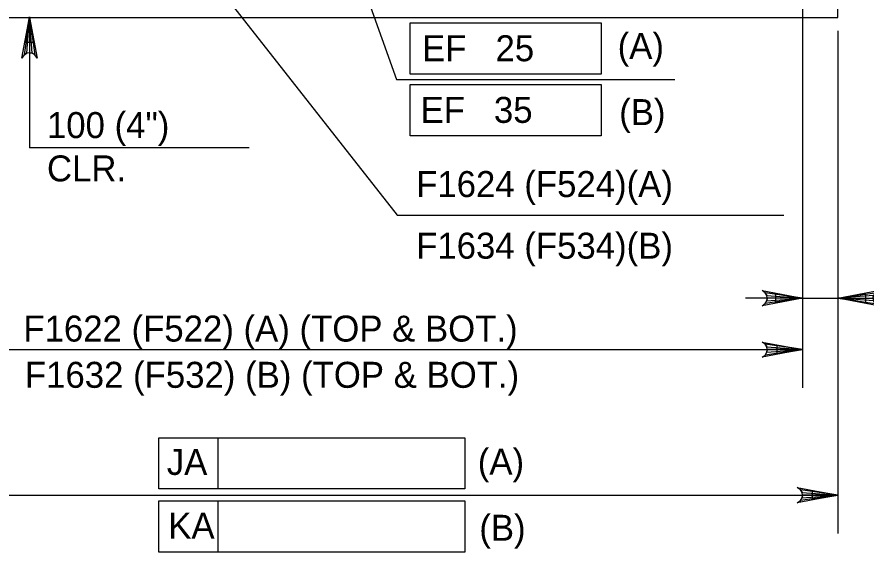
# Model space of a CAD drawing. Extents: x 634540 to 640306, y 296059 to 300275.
# Drawn here: x 639950.5 to 640048.5, y 298123.5 to 298185.3 of the extents above; entities that cross this region are included whole.
import ezdxf

# ---------------------------------------------------------------- set-up
doc = ezdxf.new("R2010")
doc.units = 0
for name, color, linetype in [('3', 7, 'Continuous'), ('4', 7, 'Continuous'), ('6', 7, 'Continuous'), ('9', 7, 'Continuous')]:
    doc.layers.add(name, color=color, linetype=linetype)

msp = doc.modelspace()

# ---------------------------------------------------------------- linework, layer by layer
at = {"layer": '4'}
for p, q in [((639964.766, 298200.154), (639994.343, 298162.419)), ((639989.636, 298191.057), (639994.297, 298178.094)), ((640041.155, 298188.247), (640041.155, 298142.484)), ((639995.87, 298184.624), (640017.91, 298184.624)), ((639995.87, 298178.717), (639995.87, 298184.624)), ((640017.91, 298184.624), (640017.91, 298178.717)), ((640045.22, 298183.697), (640045.22, 298125.682)), ((639951.891, 298182.901), (639951.891, 298170.206)), ((640017.91, 298178.717), (639995.87, 298178.717)), ((639994.297, 298178.094), (640026.409, 298178.094)), ((639995.87, 298177.511), (640017.91, 298177.511)), ((639995.87, 298171.604), (639995.87, 298177.511)), ((640017.91, 298177.511), (640017.91, 298171.604)), ((640017.91, 298171.604), (639995.87, 298171.604)), ((640045.22, 298163.383), (640045.22, 298151.891)), ((639994.343, 298162.419), (640039.009, 298162.419)), ((640041.155, 298152.847), (640034.565, 298152.847)), ((640041.155, 298152.847), (640074.917, 298152.847)), ((639935.009, 298146.914), (640041.155, 298146.914)), ((639966.86, 298136.74), (640002.162, 298136.74)), ((639966.86, 298130.834), (639966.86, 298136.74)), ((639973.704, 298130.834), (639973.704, 298136.74)), ((640002.162, 298136.74), (640002.162, 298130.834)), ((640002.162, 298130.834), (639966.86, 298130.834)), ((639930.942, 298130.111), (640045.22, 298130.111)), ((639966.86, 298129.455), (640002.162, 298129.455)), ((639966.86, 298123.548), (639966.86, 298129.455)), ((639973.704, 298123.548), (639973.704, 298129.455)), ((640002.162, 298129.455), (640002.162, 298123.548)), ((640002.162, 298123.548), (639966.86, 298123.548))]:
    msp.add_line(p, q, dxfattribs=at)
for points in [[(639951.903, 298185.234), (639952.778, 298180.574), (639952.528, 298180.932), (639952.216, 298181.117), (639951.903, 298181.172), (639951.591, 298181.117), (639951.278, 298180.932), (639951.03, 298180.574), (639951.903, 298185.234), (639951.278, 298180.932), (639951.591, 298181.117), (639951.903, 298185.234), (639951.903, 298181.172), (639952.216, 298181.117), (639951.903, 298185.234), (639952.528, 298180.932)], [(640041.155, 298152.847), (640036.495, 298151.974), (640036.853, 298152.222), (640037.038, 298152.535), (640037.093, 298152.847), (640037.038, 298153.16), (640036.853, 298153.472), (640036.495, 298153.72), (640041.155, 298152.847), (640036.853, 298153.472), (640037.038, 298153.16), (640041.155, 298152.847), (640037.093, 298152.847), (640037.038, 298152.535), (640041.155, 298152.847), (640036.853, 298152.222)], [(640045.22, 298152.847), (640049.881, 298153.72), (640049.522, 298153.472), (640049.337, 298153.16), (640049.283, 298152.847), (640049.337, 298152.535), (640049.522, 298152.222), (640049.881, 298151.974), (640045.22, 298152.847), (640049.522, 298152.222), (640049.337, 298152.535), (640045.22, 298152.847), (640049.283, 298152.847), (640049.337, 298153.16), (640045.22, 298152.847), (640049.522, 298153.472)], [(640041.155, 298146.914), (640036.495, 298146.041), (640036.853, 298146.289), (640037.038, 298146.601), (640037.093, 298146.914), (640037.038, 298147.226), (640036.853, 298147.539), (640036.495, 298147.787), (640041.155, 298146.914), (640036.853, 298147.539), (640037.038, 298147.226), (640041.155, 298146.914), (640037.093, 298146.914), (640037.038, 298146.601), (640041.155, 298146.914), (640036.853, 298146.289)], [(640045.22, 298130.111), (640040.559, 298129.238), (640040.918, 298129.486), (640041.103, 298129.798), (640041.157, 298130.111), (640041.103, 298130.423), (640040.918, 298130.736), (640040.559, 298130.984), (640045.22, 298130.111), (640040.918, 298130.736), (640041.103, 298130.423), (640045.22, 298130.111), (640041.157, 298130.111), (640041.103, 298129.798), (640045.22, 298130.111), (640040.918, 298129.486)]]:
    msp.add_lwpolyline(points, dxfattribs=at)
for points in [[(639952.382, 298182.359), (639951.399, 298182.359), (639951.891, 298185.311)], [(640038.068, 298152.356), (640038.068, 298153.341), (640041.02, 298152.847)], [(640048.447, 298153.341), (640048.447, 298152.356), (640045.495, 298152.847)], [(640038.203, 298147.405), (640038.203, 298146.422), (640041.155, 298146.914)], [(640042.268, 298130.603), (640042.268, 298129.619), (640045.22, 298130.111)]]:
    msp.add_lwpolyline(points, close=True, dxfattribs=at)
at = {"layer": '6'}
msp.add_line((639977.264, 298170.207), (639951.892, 298170.207), dxfattribs=at)
at = {"layer": '9'}
for p, q in [((640045.22, 298185.234), (640045.22, 298209.842)), ((639930.942, 298185.234), (640045.22, 298185.234))]:
    msp.add_line(p, q, dxfattribs=at)

# ---------------------------------------------------------------- texts
at = {"layer": '3'}
for s, p in [('100 (4")', (639953.924, 298171.334)), ('CLR.', (639953.924, 298166.333))]:
    msp.add_text(s, height=3.0001, dxfattribs=at).set_placement(p)
at = {"layer": '4'}
for s, height, p in [('(A)', 3.0001, (640019.815, 298180.476)), ('EF   25', 3.0001, (639997.241, 298180.203)), ('EF   35', 3.0001, (639997.059, 298173.088)), ('(B)', 3.0001, (640019.992, 298172.832)), ('F1624 (F524)(A)', 3.00014, (639996.547, 298164.525)), ('F1634 (F534)(B)', 3.00014, (639996.547, 298157.412)), ('F1622 (F522) (A) (TOP & BOT.)', 3.00014, (639951.199, 298147.841)), ('F1632 (F532) (B) (TOP & BOT.)', 3.00014, (639951.376, 298142.503)), ('JA', 3.0001, (639967.76, 298132.446)), ('(A)', 3.0001, (640003.666, 298132.492)), ('KA', 3.0001, (639967.931, 298125.096)), ('(B)', 3.0001, (640003.843, 298124.848))]:
    msp.add_text(s, height=height, dxfattribs=at).set_placement(p)

doc.saveas('drawing.dxf')
